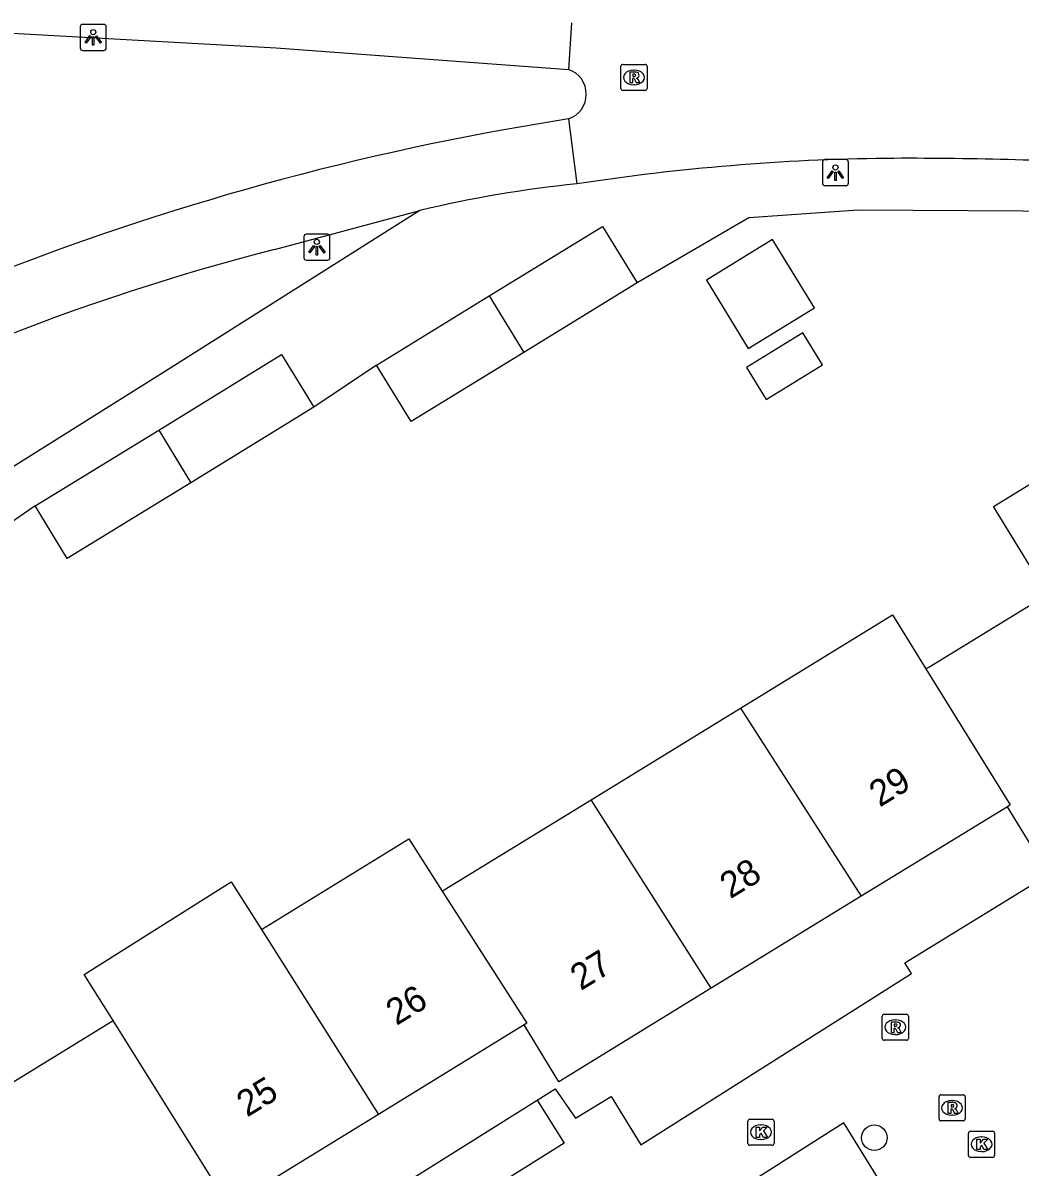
# Model space of a CAD drawing. Extents: x 158461 to 159795, y 387220 to 388672.
# Drawn here: x 158791.15 to 158829.32, y 388032.14 to 388075.95 of the extents above; entities that cross this region are included whole.
import ezdxf

# ---------------------------------------------------------------- set-up
doc = ezdxf.new("R2010")
doc.units = 0
for name, color, linetype in [('IMGEO_Boom', 7, 'Continuous'), ('IMGEO_Fietspad_gesloten', 7, 'Continuous'), ('IMGEO_Fietspad_open', 7, 'Continuous'), ('IMGEO_Kolk', 7, 'Continuous'), ('IMGEO_Lichtpunt', 7, 'Continuous'), ('IMGEO_Pand', 7, 'Continuous'), ('IMGEO_Pand_nummerreeks', 7, 'Continuous'), ('IMGEO_Parkeervlak_open', 7, 'Continuous'), ('IMGEO_Rijbaan_lokaal_open', 7, 'Continuous'), ('IMGEO_Rioolput', 7, 'Continuous'), ('IMGEO_Voetpad_open', 7, 'Continuous')]:
    doc.layers.add(name, color=color, linetype=linetype)

msp = doc.modelspace()

# ---------------------------------------------------------------- linework, layer by layer
at = {"layer": 'IMGEO_Boom'}
msp.add_circle((158823.744, 388033.262), 0.489, dxfattribs=at)
at = {"layer": 'IMGEO_Fietspad_gesloten'}
for points in [[(158812.157, 388075.952), (158812.157, 388075.952), (158812.036, 388074.165)], [(158812.035, 388072.281), (158812.353, 388069.785)]]:
    msp.add_lwpolyline(points, dxfattribs=at)
for centre, radius, start, end in [((158811.727, 388073.223), 0.991, 288.1213, 71.8179), ((158825.164, 387986.84), 83.929, 90.659, 98.78022), ((158825.119, 387927.82), 142.946, 86.63157, 90.36876)]:
    msp.add_arc(centre, radius, start, end, dxfattribs=at)
at = {"layer": 'IMGEO_Fietspad_open'}
for points in [[(158787.791, 388075.652), (158788.897, 388075.66), (158800.847, 388074.994), (158812.036, 388074.165)], [(158812.035, 388072.281), (158809.643, 388071.873)], [(158800.787, 388067.276), (158806.347, 388068.767)]]:
    msp.add_lwpolyline(points, dxfattribs=at)
for centre, radius, start, end in [((158828.197, 387968.776), 104.754, 100.20211, 112.97598), ((158816.767, 388025.519), 44.486, 95.6941, 103.546), ((158822.351, 387982.893), 87.095, 104.33498, 119.47372)]:
    msp.add_arc(centre, radius, start, end, dxfattribs=at)
at = {"layer": 'IMGEO_Kolk'}
for p, q in [((158818.903, 388033.045), (158818.903, 388033.897)), ((158818.978, 388033.971), (158819.83, 388033.971)), ((158819.904, 388033.897), (158819.904, 388033.045)), ((158819.391, 388033.751), (158819.416, 388033.751)), ((158827.346, 388032.584), (158827.346, 388033.436)), ((158827.421, 388033.51), (158828.273, 388033.51)), ((158828.347, 388033.436), (158828.347, 388032.584)), ((158819.83, 388032.971), (158818.978, 388032.971)), ((158819.414, 388033.191), (158819.389, 388033.191)), ((158827.834, 388033.29), (158827.859, 388033.29)), ((158828.273, 388032.51), (158827.421, 388032.51)), ((158827.857, 388032.73), (158827.832, 388032.73))]:
    msp.add_line(p, q, dxfattribs=at)
for points in [[(158818.903, 388033.045), (158818.903, 388033.897)], [(158818.978, 388033.971), (158819.83, 388033.971)], [(158819.904, 388033.897), (158819.904, 388033.045)], [(158819.224, 388033.671), (158819.347, 388033.671), (158819.347, 388033.52), (158819.477, 388033.671), (158819.641, 388033.671), (158819.495, 388033.52), (158819.648, 388033.271), (158819.496, 388033.271), (158819.411, 388033.435), (158819.347, 388033.368), (158819.347, 388033.271), (158819.224, 388033.271), (158819.224, 388033.671)], [(158827.346, 388032.584), (158827.346, 388033.436)], [(158827.421, 388033.51), (158828.273, 388033.51)], [(158828.347, 388033.436), (158828.347, 388032.584)], [(158819.83, 388032.971), (158818.978, 388032.971)], [(158827.667, 388033.21), (158827.79, 388033.21), (158827.79, 388033.059), (158827.92, 388033.21), (158828.084, 388033.21), (158827.938, 388033.059), (158828.091, 388032.81), (158827.939, 388032.81), (158827.854, 388032.974), (158827.79, 388032.907), (158827.79, 388032.81), (158827.667, 388032.81), (158827.667, 388033.21)], [(158828.273, 388032.51), (158827.421, 388032.51)]]:
    msp.add_lwpolyline(points, dxfattribs=at)
for centre, start, end in [((158818.98, 388033.895), 91.552, 178.448), ((158818.98, 388033.895), 91.552, 178.448), ((158819.828, 388033.895), 1.552, 88.448), ((158819.828, 388033.895), 1.552, 88.448), ((158827.423, 388033.434), 91.552, 178.448), ((158827.423, 388033.434), 91.552, 178.448), ((158828.271, 388033.434), 1.552, 88.448), ((158828.271, 388033.434), 1.552, 88.448), ((158818.98, 388033.047), 181.552, 268.448), ((158818.98, 388033.047), 181.552, 268.448), ((158819.828, 388033.047), 271.552, 358.448), ((158819.828, 388033.047), 271.552, 358.448), ((158827.423, 388032.586), 181.552, 268.448), ((158827.423, 388032.586), 181.552, 268.448), ((158828.271, 388032.586), 271.552, 358.448), ((158828.271, 388032.586), 271.552, 358.448)]:
    msp.add_arc(centre, 0.0765, start, end, dxfattribs=at)
for centre, major_axis, ratio, start_param, end_param in [((158819.39, 388033.471), (-0.387, 0.002), 0.722429, 4.712389, 7.853982), ((158819.415, 388033.471), (-0.39, 0.002), 0.717154, 1.570796, 4.712389), ((158827.833, 388033.01), (-0.387, 0.002), 0.722429, 4.712389, 7.853982), ((158827.858, 388033.01), (-0.39, 0.002), 0.717154, 1.570796, 4.712389)]:
    msp.add_ellipse(centre, major_axis=major_axis, ratio=ratio, start_param=start_param, end_param=end_param, dxfattribs=at)
at = {"layer": 'IMGEO_Lichtpunt'}
for p, q in [((158794.249, 388075.894), (158793.441, 388075.894)), ((158794.249, 388075.894), (158793.441, 388075.894)), ((158793.347, 388075.799), (158793.347, 388074.992)), ((158793.347, 388075.799), (158793.347, 388074.992)), ((158794.343, 388074.992), (158794.343, 388075.799)), ((158794.343, 388074.992), (158794.343, 388075.799)), ((158793.441, 388074.898), (158794.249, 388074.898)), ((158793.441, 388074.898), (158794.249, 388074.898)), ((158822.656, 388070.715), (158821.848, 388070.715)), ((158822.656, 388070.715), (158821.848, 388070.715)), ((158821.754, 388070.62), (158821.754, 388069.813)), ((158821.754, 388070.62), (158821.754, 388069.813)), ((158822.75, 388069.813), (158822.75, 388070.62)), ((158822.75, 388069.813), (158822.75, 388070.62)), ((158821.848, 388069.719), (158822.656, 388069.719)), ((158821.848, 388069.719), (158822.656, 388069.719)), ((158801.908, 388067.767), (158801.908, 388066.96)), ((158801.908, 388067.767), (158801.908, 388066.96)), ((158802.81, 388067.862), (158802.002, 388067.862)), ((158802.81, 388067.862), (158802.002, 388067.862)), ((158802.904, 388066.96), (158802.904, 388067.767)), ((158802.904, 388066.96), (158802.904, 388067.767)), ((158802.002, 388066.866), (158802.81, 388066.866)), ((158802.002, 388066.866), (158802.81, 388066.866))]:
    msp.add_line(p, q, dxfattribs=at)
for points in [[(158793.721, 388075.463), (158793.76, 388075.435), (158793.572, 388075.173), (158793.534, 388075.2), (158793.721, 388075.463)], [(158793.933, 388075.435), (158793.971, 388075.462), (158794.158, 388075.2), (158794.119, 388075.172), (158793.933, 388075.435)], [(158793.823, 388075.415), (158793.87, 388075.415), (158793.87, 388075.093), (158793.823, 388075.093), (158793.823, 388075.415)], [(158822.128, 388070.284), (158822.167, 388070.256), (158821.979, 388069.994), (158821.941, 388070.021), (158822.128, 388070.284)], [(158822.23, 388070.236), (158822.277, 388070.236), (158822.277, 388069.914), (158822.23, 388069.914), (158822.23, 388070.236)], [(158822.34, 388070.256), (158822.378, 388070.283), (158822.565, 388070.021), (158822.526, 388069.993), (158822.34, 388070.256)], [(158802.282, 388067.431), (158802.321, 388067.403), (158802.133, 388067.141), (158802.095, 388067.168), (158802.282, 388067.431)], [(158802.384, 388067.383), (158802.431, 388067.383), (158802.431, 388067.061), (158802.384, 388067.061), (158802.384, 388067.383)], [(158802.494, 388067.403), (158802.532, 388067.43), (158802.719, 388067.168), (158802.68, 388067.14), (158802.494, 388067.403)]]:
    msp.add_lwpolyline(points, dxfattribs=at)
for centre in [(158793.846, 388075.597), (158822.253, 388070.418), (158802.407, 388067.565)]:
    msp.add_circle(centre, 0.0994, dxfattribs=at)
for centre, start, end in [((158793.441, 388075.799), 90, 180), ((158793.441, 388075.799), 90, 180), ((158794.249, 388075.799), 0, 90), ((158794.249, 388075.799), 0, 90), ((158793.441, 388074.992), 180, 270), ((158793.441, 388074.992), 180, 270), ((158794.249, 388074.992), 270, 0), ((158794.249, 388074.992), 270, 360), ((158821.848, 388070.62), 90, 180), ((158821.848, 388070.62), 90, 180), ((158822.656, 388070.62), 0, 90), ((158822.656, 388070.62), 0, 90), ((158821.848, 388069.813), 180, 270), ((158821.848, 388069.813), 180, 270), ((158822.656, 388069.813), 270, 0), ((158822.656, 388069.813), 270, 360), ((158802.002, 388067.767), 90, 180), ((158802.002, 388067.767), 90, 180), ((158802.81, 388067.767), 0, 90), ((158802.81, 388067.767), 0, 90), ((158802.002, 388066.96), 180, 270), ((158802.002, 388066.96), 180, 270), ((158802.81, 388066.96), 270, 0), ((158802.81, 388066.96), 270, 360)]:
    msp.add_arc(centre, 0.0946, start, end, dxfattribs=at)
at = {"layer": 'IMGEO_Pand'}
for points in [[(158809.002, 388065.497), (158813.336, 388068.158), (158814.665, 388065.992)], [(158817.315, 388066.098), (158818.916, 388063.488), (158821.449, 388065.042), (158819.847, 388067.652), (158817.315, 388066.098)], [(158814.665, 388065.992), (158810.323, 388063.326)], [(158804.69, 388062.85), (158809.002, 388065.497)], [(158809.002, 388065.497), (158810.323, 388063.326)], [(158818.854, 388062.76), (158819.607, 388061.532), (158821.761, 388062.853), (158821.008, 388064.081), (158818.854, 388062.76)], [(158796.35, 388060.362), (158801.053, 388063.249), (158802.29, 388061.234)], [(158810.323, 388063.326), (158806.019, 388060.684), (158804.69, 388062.85)], [(158802.29, 388061.234), (158797.584, 388058.345)], [(158791.616, 388057.456), (158796.35, 388060.362)], [(158796.35, 388060.362), (158797.584, 388058.345)], [(158825.72, 388051.212), (158825.823, 388051.276), (158830.371, 388054.067), (158828.303, 388057.436), (158830.445, 388058.75), (158832.532, 388055.351)], [(158797.584, 388058.345), (158792.853, 388055.441), (158791.616, 388057.456)], [(158818.614, 388049.708), (158824.438, 388053.283), (158825.72, 388051.212)], [(158825.72, 388051.212), (158828.941, 388046.008), (158828.835, 388045.935)], [(158812.904, 388046.203), (158818.614, 388049.708)], [(158818.614, 388049.708), (158823.24, 388042.507)], [(158835.024, 388046.923), (158830.09, 388043.894), (158828.835, 388045.935)], [(158807.207, 388042.706), (158807.278, 388042.749), (158812.904, 388046.203)], [(158817.499, 388038.983), (158812.904, 388046.203)], [(158828.835, 388045.935), (158823.24, 388042.507)], [(158800.28, 388041.233), (158805.93, 388044.701), (158807.207, 388042.706)], [(158794.604, 388037.749), (158793.504, 388039.509), (158799.119, 388043.066), (158800.28, 388041.233)], [(158807.207, 388042.706), (158810.446, 388037.648), (158810.335, 388037.578)], [(158823.24, 388042.507), (158817.499, 388038.983)], [(158800.28, 388041.233), (158804.762, 388034.157)], [(158817.499, 388038.983), (158811.669, 388035.404), (158810.335, 388037.578)], [(158799.043, 388030.646), (158793.178, 388027.046), (158788.797, 388034.184), (158794.604, 388037.749)], [(158799.043, 388030.646), (158794.604, 388037.749)], [(158810.335, 388037.578), (158804.762, 388034.157)], [(158804.762, 388034.157), (158799.043, 388030.646)]]:
    msp.add_lwpolyline(points, dxfattribs=at)
at = {"layer": 'IMGEO_Parkeervlak_open'}
msp.add_lwpolyline([(158797.222, 388026.163), (158810.837, 388034.701)], dxfattribs=at)
at = {"layer": 'IMGEO_Rijbaan_lokaal_open'}
for points in [[(158810.837, 388034.701), (158811.531, 388035.136), (158812.3, 388034.006), (158813.67, 388034.844), (158814.809, 388032.995), (158825.165, 388039.553), (158824.905, 388039.963), (158830.273, 388043.257), (158832.611, 388039.578), (158844.906, 388047.164), (158843.887, 388048.844), (158849.176, 388052.217), (158847.555, 388054.691)], [(158810.837, 388034.701), (158811.868, 388033.058), (158798.256, 388024.516), (158797.222, 388026.163)], [(158837.364, 388009.902), (158834.472, 388014.58), (158822.574, 388033.828), (158817.624, 388030.681)]]:
    msp.add_lwpolyline(points, dxfattribs=at)
at = {"layer": 'IMGEO_Rioolput'}
for p, q in [((158814.041, 388073.438), (158814.041, 388074.29)), ((158814.116, 388074.364), (158814.968, 388074.364)), ((158814.529, 388074.144), (158814.554, 388074.144)), ((158815.042, 388074.29), (158815.042, 388073.438)), ((158814.968, 388073.364), (158814.116, 388073.364)), ((158814.552, 388073.584), (158814.527, 388073.584)), ((158824.045, 388037.065), (158824.045, 388037.917)), ((158824.12, 388037.991), (158824.972, 388037.991)), ((158824.533, 388037.771), (158824.558, 388037.771)), ((158825.046, 388037.917), (158825.046, 388037.065)), ((158824.972, 388036.991), (158824.12, 388036.991)), ((158824.556, 388037.211), (158824.531, 388037.211)), ((158826.219, 388033.98), (158826.219, 388034.832)), ((158826.294, 388034.906), (158827.146, 388034.906)), ((158827.22, 388034.832), (158827.22, 388033.98)), ((158826.707, 388034.686), (158826.732, 388034.686)), ((158827.146, 388033.906), (158826.294, 388033.906)), ((158826.73, 388034.126), (158826.705, 388034.126))]:
    msp.add_line(p, q, dxfattribs=at)
for points in [[(158814.041, 388073.438), (158814.041, 388074.29)], [(158814.116, 388074.364), (158814.968, 388074.364)], [(158815.042, 388074.29), (158815.042, 388073.438)], [(158814.63, 388074.062), (158814.378, 388074.064), (158814.378, 388073.664)], [(158814.378, 388073.664), (158814.502, 388073.664), (158814.502, 388073.826), (158814.513, 388073.826)], [(158814.556, 388073.983), (158814.502, 388073.983), (158814.502, 388073.902)], [(158814.502, 388073.902), (158814.554, 388073.902)], [(158814.56, 388073.797), (158814.631, 388073.664), (158814.771, 388073.664), (158814.706, 388073.79)], [(158814.968, 388073.364), (158814.116, 388073.364)], [(158824.045, 388037.065), (158824.045, 388037.917)], [(158824.12, 388037.991), (158824.972, 388037.991)], [(158825.046, 388037.917), (158825.046, 388037.065)], [(158824.634, 388037.689), (158824.382, 388037.691), (158824.382, 388037.291)], [(158824.382, 388037.291), (158824.506, 388037.291), (158824.506, 388037.453), (158824.517, 388037.453)], [(158824.56, 388037.61), (158824.506, 388037.61), (158824.506, 388037.529)], [(158824.506, 388037.529), (158824.558, 388037.529)], [(158824.564, 388037.424), (158824.635, 388037.291), (158824.775, 388037.291), (158824.71, 388037.417)], [(158824.972, 388036.991), (158824.12, 388036.991)], [(158826.219, 388033.98), (158826.219, 388034.832)], [(158826.294, 388034.906), (158827.146, 388034.906)], [(158827.22, 388034.832), (158827.22, 388033.98)], [(158826.808, 388034.604), (158826.556, 388034.606), (158826.556, 388034.206)], [(158826.556, 388034.206), (158826.68, 388034.206), (158826.68, 388034.368), (158826.691, 388034.368)], [(158826.734, 388034.525), (158826.68, 388034.525), (158826.68, 388034.444)], [(158826.68, 388034.444), (158826.732, 388034.444)], [(158826.738, 388034.339), (158826.809, 388034.206), (158826.949, 388034.206), (158826.884, 388034.332)], [(158827.146, 388033.906), (158826.294, 388033.906)]]:
    msp.add_lwpolyline(points, dxfattribs=at)
for centre, radius, start, end in [((158814.118, 388074.288), 0.0765, 91.552, 178.448), ((158814.118, 388074.288), 0.0765, 91.552, 178.448), ((158814.966, 388074.288), 0.0765, 1.552, 88.448), ((158814.966, 388074.288), 0.0765, 1.552, 88.448), ((158814.512, 388073.773), 0.0533, 26.0293, 88.6989), ((158814.538, 388074.091), 0.19, 274.7715, 282.9687), ((158814.562, 388073.887), 0.0964, 77.0061, 93.1865), ((158814.576, 388073.944), 0.0378, 276.6634, 79.6772), ((158814.629, 388073.952), 0.109, 350.3612, 89.416), ((158814.627, 388073.952), 0.112, 277.5842, 350.9817), ((158814.611, 388073.737), 0.108, 29.5134, 73.7905), ((158814.118, 388073.44), 0.0765, 181.552, 268.448), ((158814.118, 388073.44), 0.0765, 181.552, 268.448), ((158814.966, 388073.44), 0.0765, 271.552, 358.448), ((158814.966, 388073.44), 0.0765, 271.552, 358.448), ((158824.122, 388037.915), 0.0765, 91.552, 178.448), ((158824.122, 388037.915), 0.0765, 91.552, 178.448), ((158824.97, 388037.915), 0.0765, 1.552, 88.448), ((158824.97, 388037.915), 0.0765, 1.552, 88.448), ((158824.516, 388037.4), 0.0533, 26.0293, 88.6989), ((158824.542, 388037.718), 0.19, 274.7715, 282.9687), ((158824.566, 388037.514), 0.0964, 77.0061, 93.1865), ((158824.58, 388037.571), 0.0378, 276.6634, 79.6772), ((158824.633, 388037.579), 0.109, 350.3612, 89.416), ((158824.631, 388037.579), 0.112, 277.5842, 350.9817), ((158824.615, 388037.364), 0.108, 29.5134, 73.7905), ((158824.122, 388037.067), 0.0765, 181.552, 268.448), ((158824.122, 388037.067), 0.0765, 181.552, 268.448), ((158824.97, 388037.067), 0.0765, 271.552, 358.448), ((158824.97, 388037.067), 0.0765, 271.552, 358.448), ((158826.296, 388034.83), 0.0765, 91.552, 178.448), ((158826.296, 388034.83), 0.0765, 91.552, 178.448), ((158827.144, 388034.83), 0.0765, 1.552, 88.448), ((158827.144, 388034.83), 0.0765, 1.552, 88.448), ((158826.69, 388034.315), 0.0533, 26.0293, 88.6989), ((158826.716, 388034.633), 0.19, 274.7715, 282.9687), ((158826.74, 388034.429), 0.0964, 77.0061, 93.1865), ((158826.754, 388034.486), 0.0378, 276.6634, 79.6772), ((158826.807, 388034.494), 0.109, 350.3612, 89.416), ((158826.805, 388034.494), 0.112, 277.5842, 350.9817), ((158826.789, 388034.279), 0.108, 29.5134, 73.7905), ((158826.296, 388033.982), 0.0765, 181.552, 268.448), ((158826.296, 388033.982), 0.0765, 181.552, 268.448), ((158827.144, 388033.982), 0.0765, 271.552, 358.448), ((158827.144, 388033.982), 0.0765, 271.552, 358.448)]:
    msp.add_arc(centre, radius, start, end, dxfattribs=at)
for centre, major_axis, ratio, start_param, end_param in [((158814.528, 388073.864), (-0.387, 0.002), 0.722429, 4.712389, 7.853982), ((158814.553, 388073.864), (-0.39, 0.002), 0.717154, 1.570796, 4.712389), ((158824.532, 388037.491), (-0.387, 0.002), 0.722429, 4.712389, 7.853982), ((158824.557, 388037.491), (-0.39, 0.002), 0.717154, 1.570796, 4.712389), ((158826.706, 388034.406), (-0.387, 0.002), 0.722429, 4.712389, 7.853982), ((158826.731, 388034.406), (-0.39, 0.002), 0.717154, 1.570796, 4.712389)]:
    msp.add_ellipse(centre, major_axis=major_axis, ratio=ratio, start_param=start_param, end_param=end_param, dxfattribs=at)
at = {"layer": 'IMGEO_Voetpad_open'}
for points in [[(158806.347, 388068.767), (158796.818, 388062.746), (158777.07, 388050.354)], [(158848.571, 388066.255), (158848.611, 388067.269), (158831.531, 388068.73), (158823.126, 388068.776), (158818.939, 388068.489), (158814.665, 388065.992)], [(158804.69, 388062.85), (158802.29, 388061.234)], [(158791.616, 388057.456), (158789.479, 388055.981)]]:
    msp.add_lwpolyline(points, dxfattribs=at)

# ---------------------------------------------------------------- texts
at = {"layer": 'IMGEO_Pand_nummerreeks'}
for s, rotation, p in [('29', 31.5471, (158823.948, 388045.899)), ('28', 31.5449, (158818.231, 388042.388)), ('27', 31.5471, (158812.506, 388038.875)), ('26', 31.5413, (158805.452, 388037.538)), ('25', 31.5413, (158799.733, 388034.027))]:
    msp.add_text(s, height=1, rotation=rotation, dxfattribs=at).set_placement(p)

doc.saveas('drawing.dxf')
